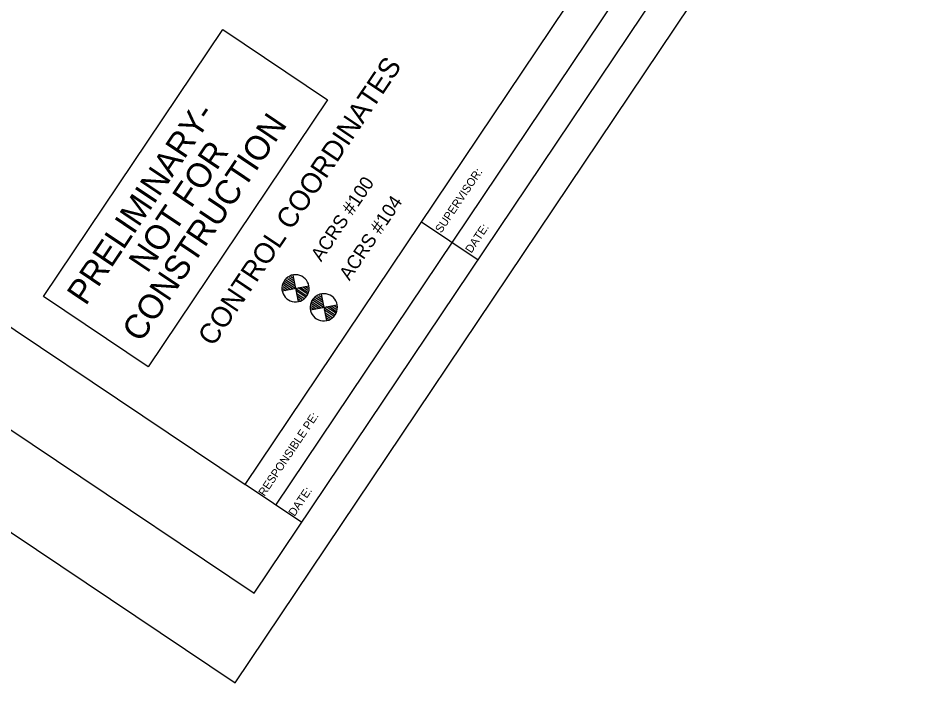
# Model space of a CAD drawing. Extents: x 1797784 to 1799645, y 248583 to 250607.
# Drawn here: x 1798538 to 1799207, y 248583 to 249071 of the extents above; entities that cross this region are included whole.
import ezdxf

# ---------------------------------------------------------------- set-up
doc = ezdxf.new("R2010")
doc.units = 0
for name, color, linetype in [('1', 7, 'Continuous'), ('ANNO-TXT', 7, 'Continuous'), ('AXIS', 7, 'Continuous'), ('CLOSURE', 7, 'Continuous'), ('Default', 7, 'Continuous'), ('Level 31', 7, 'Continuous'), ('Level 45', 7, 'Continuous'), ('Level 62', 7, 'Continuous'), ('SHT-BDR', 7, 'Continuous'), ('SHT-BNDRY', 7, 'Continuous')]:
    doc.layers.add(name, color=color, linetype=linetype)

# ---------------------------------------------------------------- blocks, each defined once
blk = doc.blocks.new('POINT_DISPLAY')
at = {"layer": 'Default'}
blk.add_line((0, 0), (0, 0), dxfattribs=at)

msp = doc.modelspace()

# ---------------------------------------------------------------- linework, layer by layer
at = {"layer": '1'}
msp.add_lwpolyline([(1798556.93, 248866.41), (1798688.72, 249062.7), (1798765.62, 249011.06), (1798633.84, 248814.78)], close=True, dxfattribs=at)
at = {"layer": 'CLOSURE'}
for p, q in [((1798739.21, 248881.99), (1798737.78, 248881.44)), ((1798740.7, 248882.31), (1798739.21, 248881.99)), ((1798740.15, 248882.12), (1798744.01, 248862.7)), ((1798742.23, 248882.41), (1798740.7, 248882.31)), ((1798743.75, 248882.27), (1798742.23, 248882.41)), ((1798745.24, 248881.9), (1798743.75, 248882.27)), ((1798746.65, 248881.3), (1798745.24, 248881.9)), ((1798732.72, 248875.93), (1798732.29, 248874.46)), ((1798733.37, 248877.32), (1798732.72, 248875.93)), ((1798733.12, 248875.2), (1798738.38, 248871.68)), ((1798734.22, 248878.59), (1798733.37, 248877.32)), ((1798733.58, 248876.49), (1798740.23, 248872.04)), ((1798735.25, 248879.72), (1798734.22, 248878.59)), ((1798734.32, 248877.6), (1798749.84, 248867.22)), ((1798735.06, 248878.71), (1798741.71, 248874.26)), ((1798736.45, 248880.67), (1798735.25, 248879.72)), ((1798736.08, 248879.63), (1798741.35, 248876.11)), ((1798737.78, 248881.44), (1798736.45, 248880.67)), ((1798737.38, 248880.37), (1798740.98, 248877.96)), ((1798738.67, 248881.1), (1798740.61, 248879.81)), ((1798747.95, 248880.5), (1798746.65, 248881.3)), ((1798749.12, 248879.51), (1798747.95, 248880.5)), ((1798750.12, 248878.35), (1798749.12, 248879.51)), ((1798750.94, 248877.06), (1798750.12, 248878.35)), ((1798751.54, 248875.65), (1798750.94, 248877.06)), ((1798751.92, 248874.17), (1798751.54, 248875.65)), ((1798732.29, 248874.46), (1798732.09, 248872.94)), ((1798732.09, 248872.94), (1798732.13, 248871.41)), ((1798732.13, 248871.41), (1798732.4, 248869.9)), ((1798732.37, 248870.48), (1798751.79, 248874.34)), ((1798732.4, 248869.9), (1798732.9, 248868.45)), ((1798732.74, 248872.24), (1798734.68, 248870.94)), ((1798732.9, 248868.45), (1798733.61, 248867.1)), ((1798732.93, 248873.72), (1798736.53, 248871.31)), ((1798749.1, 248866.11), (1798742.45, 248870.56)), ((1798742.81, 248868.71), (1798748.08, 248865.19)), ((1798750.58, 248868.33), (1798743.93, 248872.78)), ((1798745.78, 248873.14), (1798751.04, 248869.62)), ((1798747.63, 248873.51), (1798751.23, 248871.1)), ((1798749.48, 248873.88), (1798751.42, 248872.58)), ((1798750.39, 248866.85), (1798751.14, 248868.18)), ((1798751.14, 248868.18), (1798751.68, 248869.62)), ((1798751.68, 248869.62), (1798752, 248871.11)), ((1798752.08, 248872.64), (1798751.92, 248874.17)), ((1798752, 248871.11), (1798752.08, 248872.64)), ((1798761.46, 248868.38), (1798759.96, 248868.05)), ((1798760.91, 248868.18), (1798764.76, 248848.76)), ((1798762.98, 248868.47), (1798761.46, 248868.38)), ((1798764.51, 248868.33), (1798762.98, 248868.47)), ((1798765.99, 248867.96), (1798764.51, 248868.33)), ((1798733.61, 248867.1), (1798734.52, 248865.87)), ((1798734.52, 248865.87), (1798735.6, 248864.79)), ((1798735.6, 248864.79), (1798736.84, 248863.89)), ((1798736.84, 248863.89), (1798738.2, 248863.19)), ((1798738.2, 248863.19), (1798739.66, 248862.71)), ((1798739.66, 248862.71), (1798741.17, 248862.45)), ((1798741.17, 248862.45), (1798742.7, 248862.43)), ((1798742.7, 248862.43), (1798744.21, 248862.64)), ((1798743.18, 248866.86), (1798746.78, 248864.45)), ((1798743.55, 248865.01), (1798745.49, 248863.71)), ((1798744.21, 248862.64), (1798745.68, 248863.08)), ((1798745.68, 248863.08), (1798747.06, 248863.74)), ((1798747.06, 248863.74), (1798748.33, 248864.6)), ((1798748.33, 248864.6), (1798749.45, 248865.65)), ((1798749.45, 248865.65), (1798750.39, 248866.85)), ((1798753.48, 248861.99), (1798753.05, 248860.52)), ((1798754.12, 248863.38), (1798753.48, 248861.99)), ((1798754.97, 248864.65), (1798754.12, 248863.38)), ((1798754.34, 248862.55), (1798760.99, 248858.11)), ((1798756.01, 248865.78), (1798754.97, 248864.65)), ((1798755.08, 248863.66), (1798770.59, 248853.28)), ((1798755.82, 248864.77), (1798762.47, 248860.32)), ((1798757.21, 248866.74), (1798756.01, 248865.78)), ((1798756.84, 248865.69), (1798762.1, 248862.17)), ((1798758.53, 248867.5), (1798757.21, 248866.74)), ((1798758.13, 248866.43), (1798761.74, 248864.02)), ((1798759.96, 248868.05), (1798758.53, 248867.5)), ((1798759.43, 248867.17), (1798761.37, 248865.87)), ((1798767.41, 248867.37), (1798765.99, 248867.96)), ((1798768.71, 248866.57), (1798767.41, 248867.37)), ((1798769.88, 248865.57), (1798768.71, 248866.57)), ((1798770.88, 248864.42), (1798769.88, 248865.57)), ((1798771.69, 248863.12), (1798770.88, 248864.42)), ((1798772.3, 248861.71), (1798771.69, 248863.12)), ((1798772.68, 248860.23), (1798772.3, 248861.71)), ((1798753.05, 248860.52), (1798752.85, 248859)), ((1798752.85, 248859), (1798752.89, 248857.47)), ((1798752.89, 248857.47), (1798753.16, 248855.97)), ((1798753.13, 248856.55), (1798772.55, 248860.4)), ((1798753.16, 248855.97), (1798753.65, 248854.52)), ((1798753.5, 248858.3), (1798755.44, 248857.01)), ((1798753.69, 248859.78), (1798757.29, 248857.37)), ((1798753.87, 248861.26), (1798759.14, 248857.74)), ((1798769.85, 248852.18), (1798763.2, 248856.62)), ((1798763.57, 248854.77), (1798768.83, 248851.25)), ((1798771.34, 248854.39), (1798764.69, 248858.84)), ((1798766.54, 248859.21), (1798771.8, 248855.69)), ((1798768.38, 248859.57), (1798771.99, 248857.17)), ((1798770.23, 248859.94), (1798772.17, 248858.64)), ((1798771.9, 248854.25), (1798772.44, 248855.68)), ((1798772.44, 248855.68), (1798772.75, 248857.18)), ((1798772.83, 248858.71), (1798772.68, 248860.23)), ((1798772.75, 248857.18), (1798772.83, 248858.71)), ((1798753.65, 248854.52), (1798754.36, 248853.16)), ((1798754.36, 248853.16), (1798755.27, 248851.93)), ((1798755.27, 248851.93), (1798756.36, 248850.85)), ((1798756.36, 248850.85), (1798757.6, 248849.95)), ((1798757.6, 248849.95), (1798758.96, 248849.25)), ((1798758.96, 248849.25), (1798760.41, 248848.77)), ((1798760.41, 248848.77), (1798761.92, 248848.52)), ((1798761.92, 248848.52), (1798763.45, 248848.49)), ((1798763.45, 248848.49), (1798764.97, 248848.7)), ((1798763.94, 248852.92), (1798767.54, 248850.52)), ((1798764.3, 248851.08), (1798766.24, 248849.78)), ((1798764.97, 248848.7), (1798766.44, 248849.14)), ((1798766.44, 248849.14), (1798767.82, 248849.8)), ((1798767.82, 248849.8), (1798769.08, 248850.66)), ((1798769.08, 248850.66), (1798770.2, 248851.71)), ((1798770.2, 248851.71), (1798771.15, 248852.91)), ((1798771.15, 248852.91), (1798771.9, 248854.25))]:
    msp.add_line(p, q, dxfattribs=at)
at = {"layer": 'Level 62'}
msp.add_lwpolyline([(1798697.72, 248582.53), (1799645.34, 249993.92), (1798732.09, 250607.09), (1797784.47, 249195.7)], close=True, dxfattribs=at)
at = {"layer": 'SHT-BDR'}
msp.add_lwpolyline([(1798705.08, 248728.14), (1799541.22, 249973.48), (1798752.5, 250503.03), (1797916.36, 249257.69)], close=True, dxfattribs=at)
at = {"layer": 'SHT-BNDRY'}
for p, q in [((1798727.5, 248713.08), (1799161.25, 249359.12)), ((1798834.75, 248921.26), (1798876.3, 248893.36)), ((1798746.63, 248700.24), (1798705.08, 248728.14))]:
    msp.add_line(p, q, dxfattribs=at)
msp.add_lwpolyline([(1798711.8, 248648.36), (1799610.65, 249987.1), (1798738.91, 250572.4), (1797840.06, 249233.66)], close=True, dxfattribs=at)

# ---------------------------------------------------------------- block references
at = {"layer": 'CLOSURE', "xscale": 1.9999999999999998, "yscale": 1.9999999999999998, "rotation": -33.77794519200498}
for p in [(1798742.08, 248872.41), (1798762.84, 248858.47)]:
    msp.add_blockref('POINT_DISPLAY', p, dxfattribs=at)

# ---------------------------------------------------------------- texts
at = {"layer": '1'}
for s, p in [('PRELIMINARY-', (1798587.97, 248859.04)), ('CONSTRUCTION', (1798628.43, 248831.92)), ('NOT FOR', (1798633.29, 248882.86))]:
    msp.add_text(s, height=18, rotation=56.12215, dxfattribs=at).set_placement(p)
at = {"layer": 'ANNO-TXT'}
for s, p in [('SUPERVISOR:', (1798849.17, 248912.63)), ('DATE:', (1798871.25, 248897.81)), ('RESPONSIBLE PE:', (1798719.27, 248719.17)), ('DATE:', (1798741.35, 248704.35))]:
    msp.add_text(s, height=6, rotation=56.12215, dxfattribs=at).set_placement(p)
at = {"layer": 'AXIS'}
msp.add_text('-', height=3.3413287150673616e-18, rotation=109.25225, dxfattribs=at).set_placement((1798663.57, 248756.01))
at = {"layer": 'Level 31'}
for s, p in [('ACRS #100', (1798760.91, 248891.49)), ('ACRS #104', (1798781.68, 248877.56))]:
    msp.add_text(s, height=10, rotation=56.12219, dxfattribs=at).set_placement(p)
at = {"layer": 'Level 45'}
msp.add_text('CONTROL COORDINATES', height=14.8986, rotation=56.12219, dxfattribs=at).set_placement((1798681.67, 248829.05))

doc.saveas('drawing.dxf')
